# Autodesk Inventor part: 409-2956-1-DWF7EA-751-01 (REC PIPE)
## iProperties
Created: 2010-06
Part Number: 409-2956-1-DWF7EA-751-01 (REC PIPE)
Material: Sch40 CS PIPE SEAMLESS
Description: PIPE
Document SubType Name: Modeling
Designer: S. Boerckel
Engineer: Steve Boerckel
Mass: 958.943 g
Surface Area: 638.46 cm^2
Volume: 122.158 cm^3
Density: 7.85 g/cm^3
Cost Center: 4"
SMR: =<COST CENTER> - <Material>
Length: 6.938 in
Title: 2"
Author: S. Boerckel
Revision Number: B
Subject: DEMIN WATER FORWARDING PUMP SKID-7EA
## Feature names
1. Extrusion1
